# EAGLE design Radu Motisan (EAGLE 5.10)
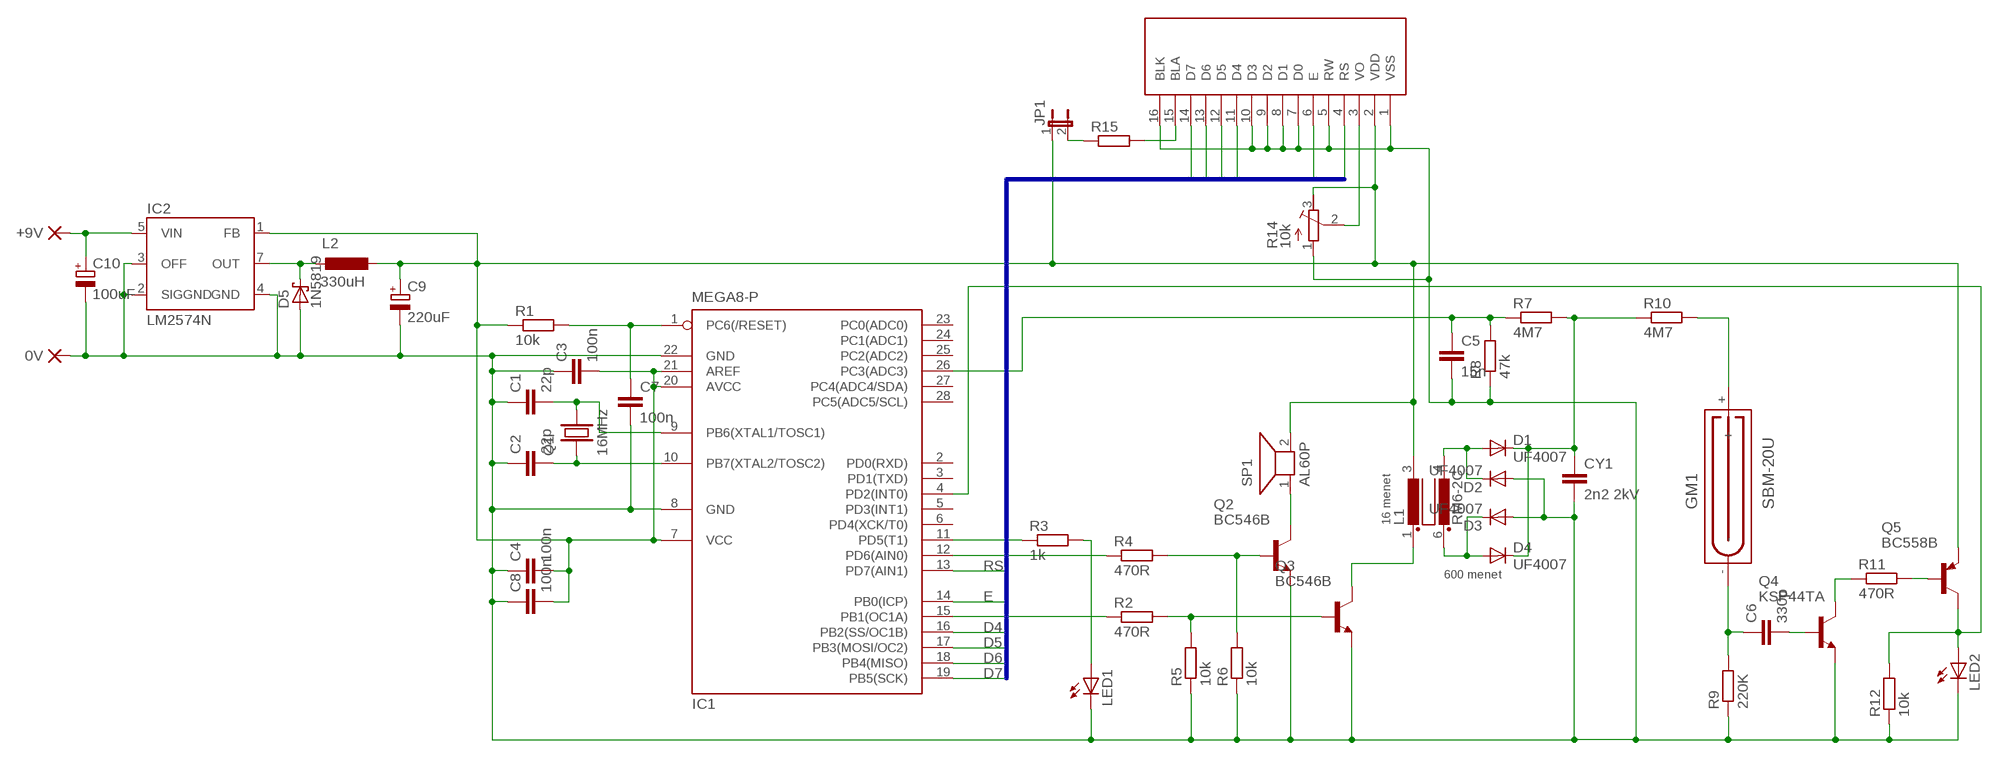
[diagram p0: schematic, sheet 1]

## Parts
0V  PAD-0460-S  [0460-S]
+9V  PAD-0460  [0460]
C1  22p  C-EU025-024X044  [C025-024X044]
C2  22p  C-EU025-024X044  [C025-024X044]
C3  100n  C-EU025-024X044  [C025-024X044]
C4  100n  C-EU025-024X044  [C025-024X044]
C5  15n  C-EU050-025X075  [C050-025X075]
C6  330p  C-EU050-024X044  [C050-024X044]
C7  100n  C-EU050-024X044  [C050-024X044]
C8  100n  C-EU025-024X044  [C025-024X044]
C9  220uF  CPOL-EUE3.5-8  [E3,5-8]
C10  100uF  CPOL-EUE3.5-8  [E3,5-8]
CY1  2n2 2kV  CYYC7B5  [YC7B5]
D1  UF4007  1N4004  [DO41-10]
D2  UF4007  1N4004  [DO41-10]
D3  UF4007  1N4004  [DO41-10]
D4  UF4007  1N4004  [DO41-10]
D5  1N5819  SCHOTTKY-DIODEDO41-10  [DO41-10]
GM1  SBM-20U  [SBM-20U]
IC1  MEGA8-P  [DIL28-3]
IC2  LM2574N  [DIL-08]
JP1  JP1E  [JP1]
L1  RM6-2C  [RM6]
L2  330uH  RLB0914  [RLB0914]
LED1  LED3MM  [LED3MM]
LED2  LED3MM  [LED3MM]
Q1  16MHz  HC-49S  [HZ-49S]
Q2  BC546B  [TO92-EBC]
Q3  BC546B  [TO92-EBC]
Q4  KSP44TA  BC546B  [TO92-EBC]
Q5  BC558B  [TO92-EBC]
R1  10k  R-EU_0204/7  [0204/7]
R2  470R  R-EU_0204/7  [0204/7]
R3  1k  R-EU_0204/7  [0204/7]
R4  470R  R-EU_0204/7  [0204/7]
R5  10k  R-EU_0204/7  [0204/7]
R6  10k  R-EU_0204/7  [0204/7]
R7  4M7  R-EU_0204/7  [0204/7]
R8  47k  R-EU_0204/7  [0204/7]
R9  220K  R-EU_0207/7  [0207/7]
R10  4M7  R-EU_0207/7  [0207/7]
R11  470R  R-EU_0204/7  [0204/7]
R12  10k  R-EU_0204/7  [0204/7]
R14  10k  R-TRIMM3339P  [RTRIM3339P]
R15  R-EU_0204/7  [0204/7]
SP1  AL60P  [AL60P]
U$2  2X16LCDTOP  [2X16LCDTOP]

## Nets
LCD1: IC1.19(PB5(SCK)) U$2.14(D7)
LCD2: IC1.18(PB4(MISO)) U$2.13(D6)
LCD3: IC1.17(PB3(MOSI/OC2)) U$2.12(D5)
LCD4: IC1.16(PB2(SS/OC1B)) U$2.11(D4)
LCD5: IC1.14(PB0(ICP)) U$2.6(E)
LCD6: IC1.13(PD7(AIN1)) U$2.4(RS)
N$1: C7.1 IC1.1(PC6(/RESET)) R1.2
N$2: C3.2 C4.2 C8.2 C9.+ IC1.7(VCC) IC1.20(AVCC) IC1.21(AREF) IC2.1(FB) JP1.1 L1.3 L2.P$2 Q5.E R1.1 R14.3(A) SP1.2 U$2.2(VDD)
N$3: 0V.P$1(P) C1.1 C2.1 C3.1 C4.1 C5.2 C7.2 C8.1 C9.- C10.- CY1.2 D2.A D3.A D5.A IC1.8(GND) IC1.22(GND) IC2.2(SIGGND) IC2.3(OFF) IC2.4(GND) LED1.K(C) LED2.K(C) Q2.E Q3.E Q4.E R5.1 R6.1 R8.1 R9.1 R12.1 R14.1(E) U$2.1(VSS) U$2.5(RW) U$2.7(D0) U$2.8(D1) U$2.9(D2) U$2.10(D3) U$2.16(BLK)
N$4: C1.2 IC1.9(PB6(XTAL1/TOSC1)) Q1.P$2
N$5: C2.2 IC1.10(PB7(XTAL2/TOSC2)) Q1.P$1
N$6: IC1.15(PB1(OC1A)) R2.1
N$7: IC1.11(PD5(T1)) R3.1
N$8: IC1.12(PD6(AIN0)) R4.1
N$9: LED1.A R3.2
N$10: Q2.B R4.2 R6.2
N$11: Q3.B R2.2 R5.2
N$12: Q2.C SP1.1
N$13: L1.1 Q3.C
N$14: GM1.+ R10.2
N$15: D1.A D2.C L1.4
N$16: D3.C D4.A L1.6
N$17: CY1.1 D1.C D4.C R7.2 R10.1
N$18: R14.2(S) U$2.3(VO)
N$19: C5.1 IC1.26(PC3(ADC3)) R7.1 R8.2
N$20: JP1.2 R15.1
N$21: D5.C IC2.7(OUT) L2.P$1
N$22: C6.1 GM1.- R9.2
N$23: C6.2 Q4.B
N$24: Q4.C R11.1
N$25: Q5.B R11.2
N$26: IC1.4(PD2(INT0)) LED2.A Q5.C R12.2
N$27: R15.2 U$2.15(BLA)
N$29: +9V.P$1(P) C10.+ IC2.5(VIN)
Unconnected: IC1.2(PD0(RXD)) IC1.3(PD1(TXD)) IC1.5(PD3(INT1)) IC1.6(PD4(XCK/T0)) IC1.23(PC0(ADC0)) IC1.24(PC1(ADC1)) IC1.25(PC2(ADC2)) IC1.27(PC4(ADC4/SDA)) IC1.28(PC5(ADC5/SCL))

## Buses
LCD[1..6]

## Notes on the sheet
- 16 menet
- RS
- 600 menet
- E
- D4
- D5
- D6
- D7

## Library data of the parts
0V +9V = dpads:PAD: WIRE PAD
C1-C8 = rcl-2:C-EU: CAPACITOR, European symbol
C9 C10 = rcl-2:CPOL-EU: POLARIZED CAPACITOR, European symbol
CY1 = rcl-2:CY: Y CAPACITOR
D1-D4 = diode-1:1N4004: DIODE
D5 = diode-1:SCHOTTKY-DIODE: Schottky Diode
GM1 = geiger tube:SBM-20U: SBM-20U Russian Geiger Tube
IC1 = atmel:MEGA8-P: MICROCONTROLLER 8 Kbytes FLASH, 1 kbytes SRAM, 512 bytes EEPROM, USART, 4-channel 10 bit ADC, 2-channel 8 bit ADC Pin compatible with Atmega48, ATMega88, ATMega168 Source: avr.lbr
IC2 = v-reg-3:LM2574: National Semiconductor 0.5A "Simple Switcher"(c) 52kHz, Vout 1.23-37V (HV: 57V), Vin 40V (HV: 60V), 50µA standby current
JP1 = jumper:JP1E: JUMPER
L1 = inductors-2:RM6-2C
L2 = inductor-bourns:RLB0914
LED1 LED2 = led:LED: LED
Q1 = quarz:HC-49S
Q2-Q4 = transistor-npn:BC546*: NPN Transistor
Q5 = transistor-pnp:BC558*: PNP Transistror
R1-R12 R15 = rcl-2:R-EU_: RESISTOR, European symbol
R14 = rcl-2:R-TRIMM: Trimm resistor
SP1 = buzzer:AL60P: SPEAKER
U$2 = lcd_modules_ece:2X16LCDTOP

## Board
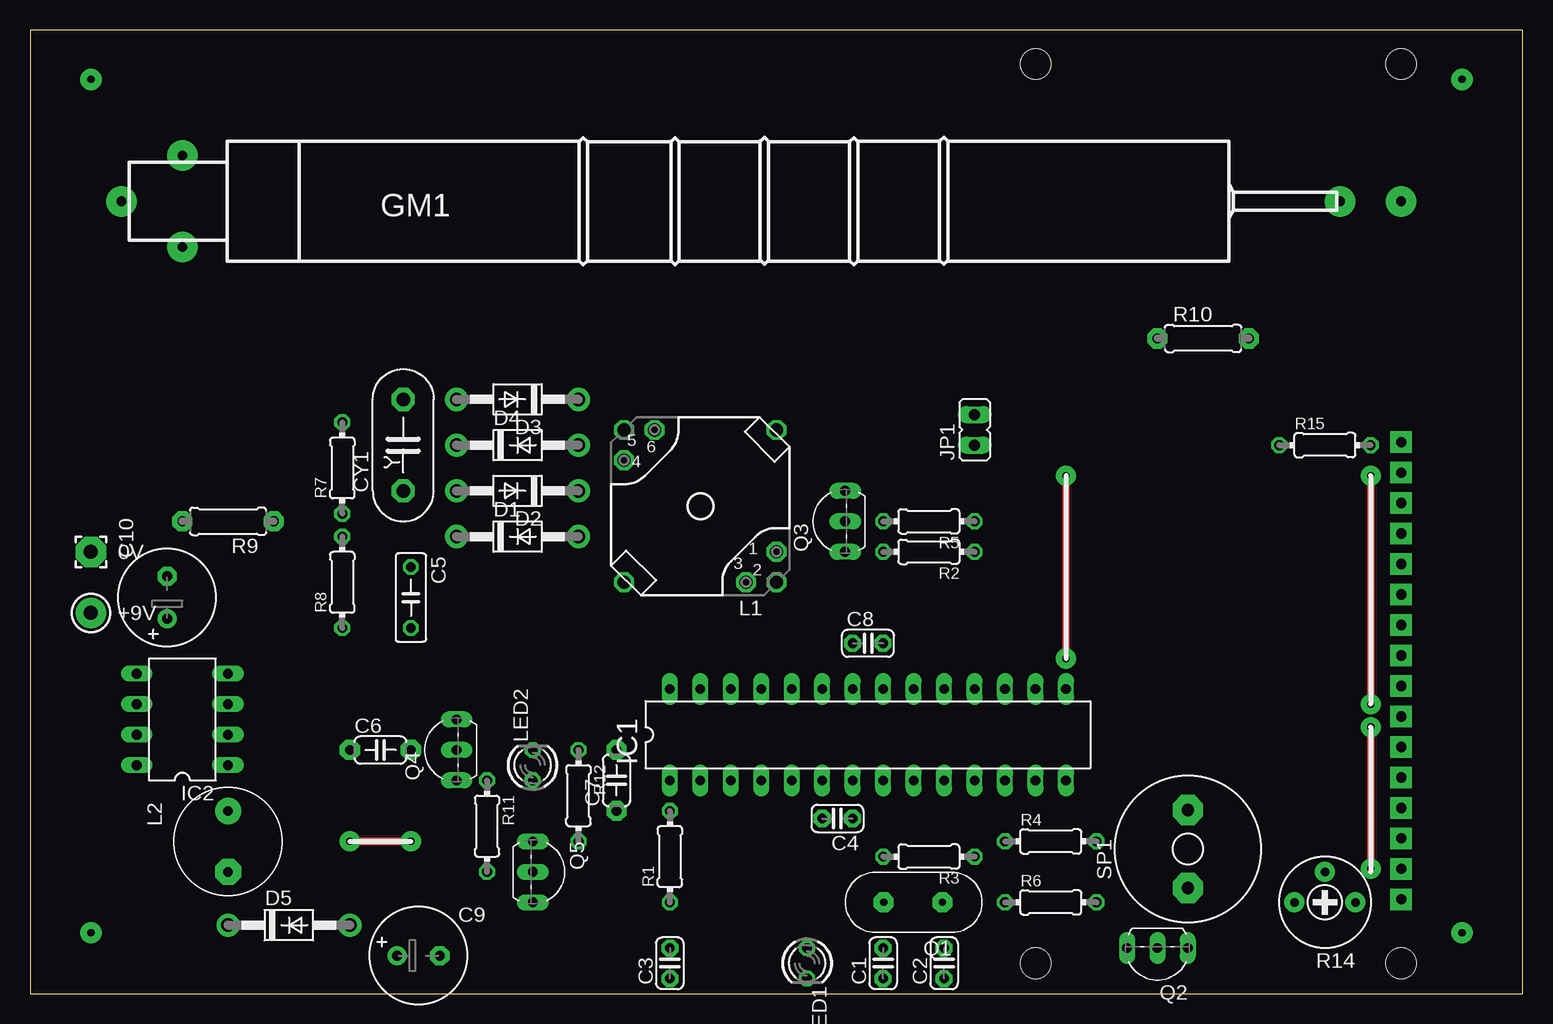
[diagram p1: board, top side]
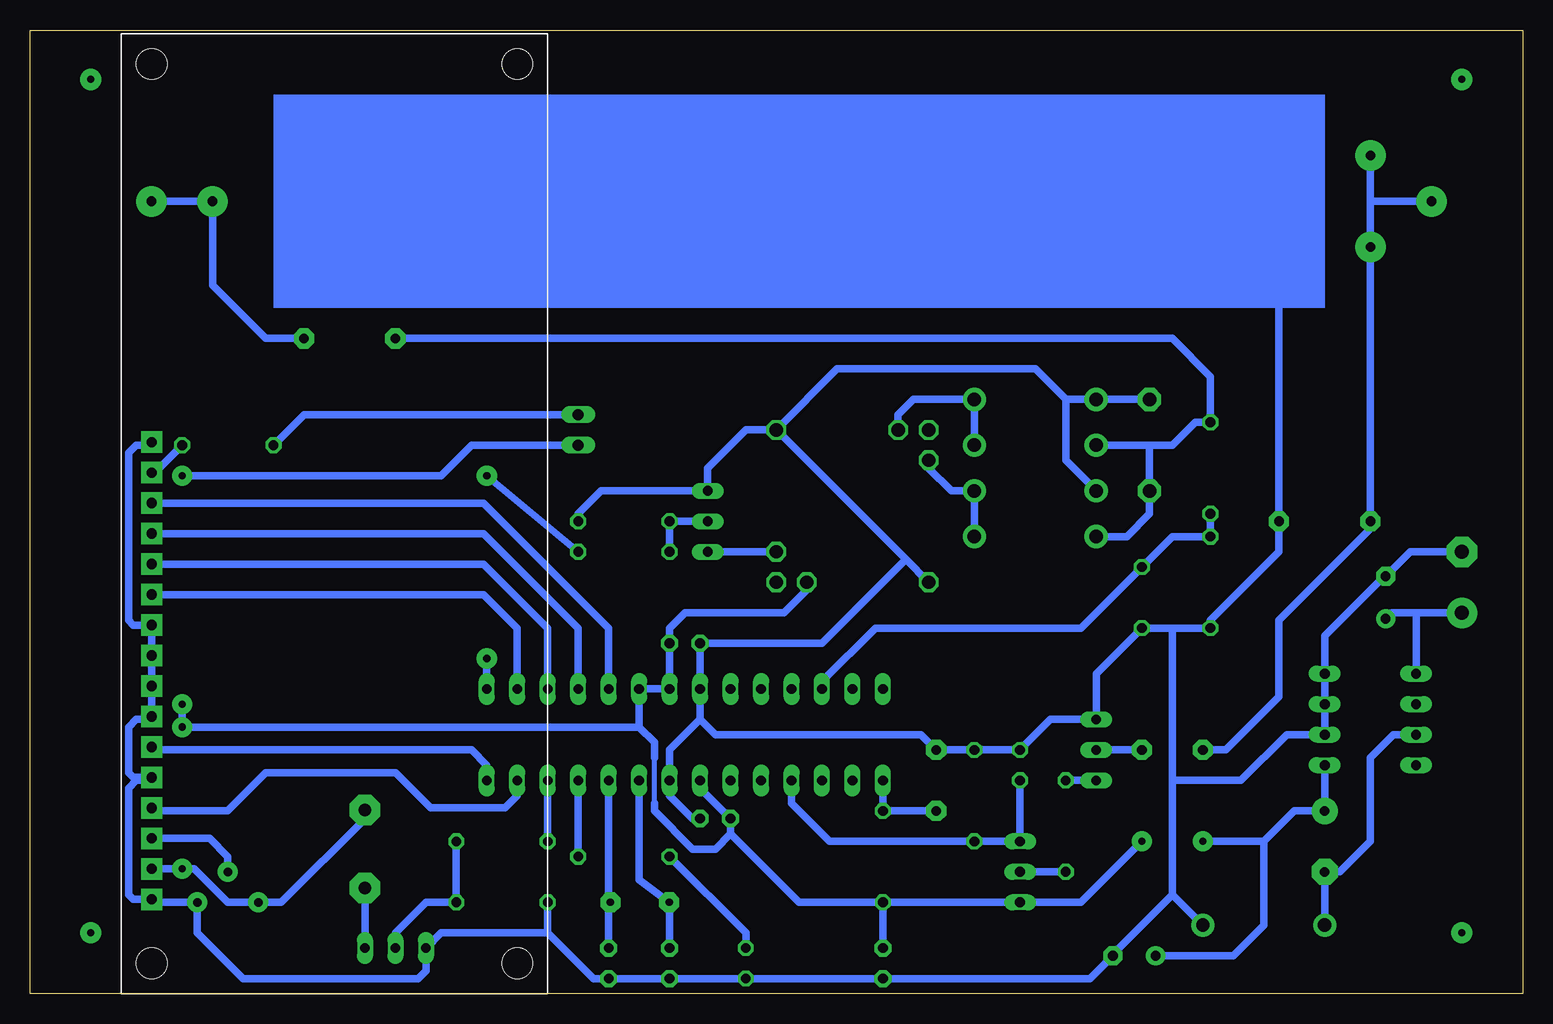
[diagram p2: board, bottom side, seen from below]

Size 124.44 x 80.31 mm. Coordinates in mm from the lower left corner, seen from the top.
Outline: 0,0 124.44,0 124.44,80.31 0,80.31 0,0
Copper layers (1*16): Top 0.035mm / dielectric 1.5mm / Bottom 0.035mm
Design rules "default": minimum track width 10mil, minimum drill 24mil, track to track 8mil, track to pad 8mil, pad to pad 8mil, via to via 8mil, smd to smd 8mil, copper to edge 40mil, drill to drill 8mil, minimum pad ring 10mil, minimum via ring 8mil, stop-mask expansion 4mil, vias tented up to drill 0mil, thermal gap 10mil

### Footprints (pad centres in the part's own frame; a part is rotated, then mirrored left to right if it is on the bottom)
0460-S = drill 1.168 pad 2.54 octagon: P$1 0,0
0460 = drill 1.168 pad 2.54 round: P$1 0,0
C025-024X044 = drill 0.813 pad 1.422 octagon: 1 -1.27,0; 2 1.27,0
C050-025X075 = drill 0.813 octagon: 1 -2.54,0; 2 2.54,0
C050-024X044 = drill 0.813 pad 1.676 octagon: 1 -2.54,0; 2 2.54,0
E3,5-8 = drill 0.813 pad 1.6 round: + -1.778,0 | drill 0.813 pad 1.6 octagon: - 1.778,0
YC7B5 = drill 1.118 pad 1.93 octagon: 1 -3.81,0; 2 3.81,0
DO41-10 = drill 1.118 pad 1.93 round: A 5.08,0; C -5.08,0
SBM-20U = drill 0.8 pad 2.54 round: + 55.88,0; - -50.8,0; P$2 -45.72,-3.81; P$3 -45.72,3.81; P$4 50.8,0
DIL28-3 = drill 0.813 long: 1 -16.51,-3.81; 2 -13.97,-3.81; 3 -11.43,-3.81; 4 -8.89,-3.81; 5 -6.35,-3.81; 6 -3.81,-3.81; 7 -1.27,-3.81; 8 1.27,-3.81; 9 3.81,-3.81; 10 6.35,-3.81; 11 8.89,-3.81; 12 11.43,-3.81; 13 13.97,-3.81; 14 16.51,-3.81; 15 16.51,3.81; 16 13.97,3.81; 17 11.43,3.81; 18 8.89,3.81; 19 6.35,3.81; 20 3.81,3.81; 21 1.27,3.81; 22 -1.27,3.81; 23 -3.81,3.81; 24 -6.35,3.81; 25 -8.89,3.81; 26 -11.43,3.81; 27 -13.97,3.81; 28 -16.51,3.81
DIL-08 = drill 0.813 long: 1 -3.81,-3.81; 2 -1.27,-3.81; 3 1.27,-3.81; 4 3.81,-3.81; 5 3.81,3.81; 6 1.27,3.81; 7 -1.27,3.81; 8 -3.81,3.81
JP1 = drill 0.914 long: 1 0,-1.27; 2 0,1.27
RM6 = drill 1.1 octagon: 1 -6.35,3.81; 2 -6.35,6.35; 3 -3.81,6.35; 4 6.35,-3.81; 5 6.35,-6.35; 6 3.81,-6.35; M1 -6.35,-6.35; M2 6.35,6.35
RLB0914 = drill 0.8 pad 2.184 octagon: P$1 -2.54,0 | drill 0.8 pad 2.184 round: P$2 2.54,0
LED3MM = drill 0.813 octagon: A -1.27,0; K 1.27,0
HZ-49S = drill 0.61 pad 1.676 octagon: P$1 -2.4,0; P$2 2.5,0
TO92-EBC = drill 0.813 long: B 0,-1.27; C -2.54,-1.27; E 2.54,-1.27
0204/7 = drill 0.813 octagon: 1 -3.81,0; 2 3.81,0
0207/7 = drill 0.813 pad 1.676 octagon: 1 -3.81,0; 2 3.81,0
RTRIM3339P = drill 0.7 pad 1.676 round: 1 -2.54,0; 2 0,-2.54; 3 2.54,0
AL60P = drill 1.016 pad 2.54 octagon: 1 -3.251,0; 2 3.251,0
2X16LCDTOP = drill 0.85 pad 1.778 square: 1 7.87,33.02; 2 10.41,33.02; 3 12.95,33.02; 4 15.49,33.02; 5 18.03,33.02; 6 20.57,33.02; 7 23.11,33.02; 8 25.65,33.02; 9 28.19,33.02; 10 30.73,33.02; 11 33.27,33.02; 12 35.81,33.02; 13 38.35,33.02; 14 40.89,33.02; 15 43.43,33.02; 16 45.97,33.02 | hole 2.54: 2.54,33.02; 77.47,33.02; 77.47,2.54; 2.54,2.54

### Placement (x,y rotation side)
0V  5.08,36.83 0 top
+9V  5.08,31.75 0 top
C1  71.12,2.54 90 top
C2  76.2,2.54 90 top
C3  53.34,2.54 90 top
C4  67.31,14.61 180 top
C5  31.75,33.02 270 top
C6  29.21,20.32 0 top
C7  48.9,17.78 90 top
C8  69.85,29.21 0 top
C9  32.38,3.17 0 top
C10  11.43,33.02 90 top
CY1  31.11,45.72 90 top
D1  40.64,38.1 0 top
D2  40.64,41.91 180 top
D3  40.64,49.53 180 top
D4  40.64,45.72 0 top
D5  21.59,5.71 0 top
GM1  58.42,66.04 0 top
IC1  69.85,21.59 0 top
IC2  12.7,22.86 90 top
JP1  78.74,46.99 0 top
L1  55.88,40.64 180 top
L2  16.51,12.7 90 top
LED1  64.77,2.54 270 top
LED2  41.91,19.05 90 top
Q1  73.66,7.62 180 top
Q2  93.98,2.54 180 top
Q3  66.67,39.37 90 top
Q4  34.29,20.32 90 top
Q5  43.18,10.16 270 top
R1  53.34,11.43 90 top
R2  74.93,36.83 180 top
R3  74.93,11.43 180 top
R4  85.09,12.7 0 top
R5  74.93,39.37 180 top
R6  85.09,7.62 0 top
R7  26.04,43.81 90 top
R8  26.04,34.29 90 top
R9  16.51,39.37 180 top
R10  97.79,54.61 0 top
R11  38.1,13.97 270 top
R12  45.72,16.51 270 top
R14  107.95,7.62 180 top
R15  107.95,45.72 0 top
SP1  96.52,12.06 90 top
U$2  81.28,0 90 bottom

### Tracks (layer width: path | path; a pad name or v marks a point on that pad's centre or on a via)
LCD1
  Bottom 0.61: U$2.14 86.61,40.89 76.2,30.48 IC1.19
LCD2
  Bottom 0.61: U$2.13 86.61,38.35 78.74,30.48 IC1.18
LCD3
  Bottom 0.61: U$2.12 86.61,35.81 81.28,30.48 IC1.17
LCD4
  Bottom 0.61: U$2.11 86.61,33.27 83.82,30.48 IC1.16
LCD5
  Bottom 0.61: IC1.14 86.36,19.05 87.63,20.32 114.05,20.32 U$2.6
LCD6
  Bottom 0.61: IC1.13 83.82,16.51 84.84,15.49 91.06,15.49 93.98,18.41 104.78,18.41 107.95,15.24 114.05,15.24 U$2.4
N$1
  Bottom 0.61: IC1.1 R1.2 C7.1
N$2  (via drill 0.6 pad 1.68)
  Top 0.61: v111.76,22.23 v111.76,10.41 | v111.76,24.13 v111.76,43.18 | v26.67,12.7 v31.75,12.7
  Bottom 0.406: 72.39,15.88 72.39,19.68
  Bottom 0.61: U$2.2 v111.76,10.41 110.74,10.41 107.95,7.62 R14.3 103.5,7.62 96.52,14.61 SP1.2 | v111.76,43.18 90.17,43.18 87.63,45.72 JP1.1 | v111.76,24.13 v111.76,22.23 73.66,22.23 | L1.3 59.69,33.66 61.59,31.75 69.85,31.75 71.12,30.48 C8.2 IC1.21 IC1.20 73.66,22.23 | IC1.7 68.58,17.14 C4.2 66.04,13.34 | 72.39,15.88 72.39,15.24 69.22,12.06 67.31,12.06 66.04,13.34 | R1.1 C3.2 | 66.04,13.34 60.33,7.62 R1.1 | R1.1 Q5.E 36.83,7.62 v31.75,12.7 | IC2.1 L2.P$2 19.05,15.24 21.59,12.7 | C9.+ 24.13,3.17 21.59,5.71 21.59,12.7 | 21.59,12.7 v26.67,12.7 | 73.66,22.23 72.39,20.95 72.39,19.68
N$3
  Bottom 0.61: U$2.16 114.55,45.72 115.57,45.72 116.2,45.09 116.2,31.11 115.82,30.73 U$2.10 U$2.9 U$2.8 U$2.7 114.55,22.86 115.57,22.86 116.2,22.23 116.2,18.41 115.82,18.03 U$2.5 114.55,17.78 115.57,17.78 116.2,17.14 116.2,8.26 115.82,7.87 U$2.1 114.05,7.62 R14.1 110.49,5.08 106.68,1.27 92.08,1.27 91.44,1.91 Q2.E 90.17,5.08 81.28,5.08 | 68.58,22.86 71.12,20.32 IC1.8 71.12,16.51 69.22,14.61 C4.1 | 68.58,22.86 IC1.22 C8.1 58.42,29.21 51.44,36.2 | R5.1 78.74,40.01 76.83,41.91 Q3.E 67.94,43.81 64.77,46.99 62.23,46.99 | CY1.2 D3.A 38.1,49.53 | D2.A 38.1,44.45 38.1,49.53 | 68.58,22.86 67.31,21.59 50.16,21.59 C7.2 R12.1 LED2.K 39.37,22.86 Q4.E 35.56,26.67 C5.2 29.21,30.48 | 29.21,30.48 R8.1 26.04,31.11 20.32,36.83 R9.1 20.32,57.78 | 29.21,8.26 34.16,3.3 C9.- 36.07,1.27 C3.1 LED1.K C1.1 C2.1 77.47,1.27 81.28,5.08 | 29.21,8.26 29.21,17.78 | 29.21,17.78 29.21,30.48 | D5.A 29.21,8.26 | 29.21,17.78 23.5,17.78 19.68,21.59 IC2.2 IC2.3 IC2.4 16.51,29.84 11.56,34.8 C10.- 9.4,36.83 0V.P$1 | 51.44,36.2 62.23,46.99 | 51.44,36.2 49.53,34.29 | 62.23,46.99 57.15,52.07 40.64,52.07 38.1,49.53 | 81.28,5.08 R6.1
N$4
  Bottom 0.61: IC1.9 73.66,9.48 Q1.P$2 71.12,7.58 C1.2
N$5
  Bottom 0.61: IC1.10 76.2,7.76 Q1.P$1 76.2,7.48 C2.2
N$6  (via drill 0.6 pad 1.68)
  Top 0.61: v86.36,27.94 v86.36,43.18
  Bottom 0.61: IC1.15 v86.36,27.94 | v86.36,43.18 R2.1
N$7
  Bottom 0.61: IC1.11 R3.1
N$8
  Bottom 0.61: IC1.12 R4.1
N$9
  Bottom 0.61: R3.2 64.77,5.08 LED1.A
N$10
  Bottom 0.61: R4.2 R6.2 91.44,7.62 93.98,5.08 Q2.B
N$11
  Bottom 0.61: Q3.B R5.2 R2.2
N$12
  Bottom 0.61: Q2.C SP1.1
N$13
  Bottom 0.61: L1.1 Q3.C
N$14
  Bottom 0.61: R10.2 104.78,54.61 109.22,59.05 109.22,66.04 GM1.+
N$15
  Bottom 0.61: L1.4 49.53,43.81 47.62,41.91 D2.C D1.A
N$16
  Bottom 0.61: D4.A D3.C 50.8,49.53 52.07,48.26 L1.6
N$17
  Bottom 0.61: D1.C 33.02,38.1 31.11,40.01 CY1.1 31.11,45.72 | R10.1 29.21,54.61 26.04,51.44 R7.2 27.3,47.62 29.21,45.72 31.11,45.72 | 31.11,45.72 D4.C
N$18
  Bottom 0.61: U$2.3 109.47,12.95 107.95,11.43 R14.2
N$19
  Bottom 0.61: IC1.26 58.42,26.04 53.98,30.48 36.83,30.48 C5.1 29.21,38.1 R8.2 R7.1
N$20
  Bottom 0.61: R15.1 101.6,48.26 JP1.2
N$21
  Bottom 0.61: D5.C L2.P$1 15.24,10.16 12.7,12.7 12.7,19.68 10.79,21.59 IC2.7
N$22
  Bottom 0.61: C6.1 24.77,20.32 20.32,24.77 20.32,31.11 12.7,38.73 R9.2 12.7,66.04 | 12.7,66.04 12.7,69.85 | 12.7,66.04 GM1.-
N$23
  Bottom 0.61: C6.2 Q4.B
N$24
  Bottom 0.61: R11.1 Q4.C
N$25
  Bottom 0.61: R11.2 Q5.B
N$26
  Bottom 0.61: IC1.4 60.96,15.88 57.78,12.7 R12.2 Q5.C LED2.A
N$27
  Bottom 0.61: U$2.15 114.05,43.43 R15.2
N$28  (via drill 0.6 pad 1.78)
  other vias: 114.3,2.54
N$29
  Bottom 0.61: 8.89,31.75 +9V.P$1 | 8.89,31.75 10.92,31.75 C10.+ | IC2.5 8.89,31.75
N$30  (via drill 0.6 pad 1.78)
  other vias: 83.82,2.54
N$31  (via drill 0.6 pad 1.78)
  other vias: 83.82,77.47
N$32  (via drill 0.6 pad 1.78)
  other vias: 114.3,77.47
N$33  (via drill 0.6 pad 1.78)
  other vias: 119.38,76.2
N$34  (via drill 0.6 pad 1.78)
  other vias: 119.38,5.08
N$35  (via drill 0.6 pad 1.78)
  other vias: 5.08,5.08
N$36  (via drill 0.6 pad 1.78)
  other vias: 5.08,76.2
(copper drawn outside any net)
  shapes: Bottom area x2

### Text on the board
Measures: LCD hátul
